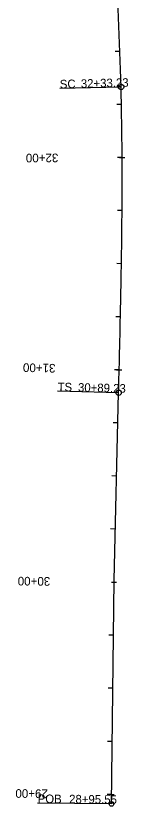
# Model space of a CAD drawing. Extents: x 21487884 to 21488802, y 8074558 to 8076894.
# Drawn here: x 21488108.5 to 21488161.4, y 8074558.2 to 8074930.5 of the extents above; entities that cross this region are included whole.
import ezdxf

# ---------------------------------------------------------------- set-up
doc = ezdxf.new("R2010")
doc.units = 0
for name, color, linetype in [('Default', 7, 'Continuous'), ('PS_BOLT', 7, 'Continuous'), ('PS_DIM', 7, 'Continuous'), ('PS_MID', 7, 'Continuous'), ('PS_SHAPE', 7, 'Continuous')]:
    doc.layers.add(name, color=color, linetype=linetype)

msp = doc.modelspace()

# ---------------------------------------------------------------- linework, layer by layer
at = {"layer": 'Default'}
msp.add_line((21488154.77, 8074664.65), (21488156.95, 8074752.94), dxfattribs=at)
msp.add_arc((21486726.15, 8074860.23), 1432.4, 1.46747, 6.70748, dxfattribs=at)
msp.add_open_spline([(21488156.95, 8074752.94), (21488157.09, 8074758.94), (21488157.39, 8074770.93), (21488157.94, 8074794.93), (21488158.5, 8074824.92), (21488158.67, 8074854.92), (21488158.47, 8074878.92), (21488158.24, 8074890.92), (21488158.08, 8074896.92)], degree=3, dxfattribs=at)
at = {"layer": 'PS_BOLT'}
for p, q in [((21488158.58, 8074863.69), (21488156.4, 8074863.68)), ((21488157.21, 8074763.7), (21488155.03, 8074763.76)), ((21488153.54, 8074663.75), (21488155.98, 8074663.72)), ((21488153.65, 8074563.74), (21488151.47, 8074563.76))]:
    msp.add_line(p, q, dxfattribs=at)
at = {"layer": 'PS_DIM'}
for p, q in [((21488158.08, 8074896.92), (21488129.29, 8074896.18)), ((21488158.08, 8074896.92), (21488129.29, 8074896.18)), ((21488156.95, 8074752.94), (21488128.16, 8074753.65)), ((21488153.61, 8074559.29), (21488118.81, 8074559.67))]:
    msp.add_line(p, q, dxfattribs=at)
for centre, radius in [((21488158.08, 8074896.92), 1.25), ((21488158.08, 8074896.92), 1.25), ((21488156.95, 8074752.94), 1.25), ((21488153.61, 8074559.29), 1.07)]:
    msp.add_circle(centre, radius, dxfattribs=at)
at = {"layer": 'PS_MID'}
for p, q in [((21488157.56, 8074913.68), (21488155.37, 8074913.6)), ((21488158.27, 8074888.69), (21488156.09, 8074888.64)), ((21488157.36, 8074863.68), (21488159.8, 8074863.7)), ((21488158.55, 8074838.69), (21488156.37, 8074838.71)), ((21488158.26, 8074813.69), (21488156.08, 8074813.73)), ((21488157.79, 8074788.7), (21488155.61, 8074788.74)), ((21488155.99, 8074763.73), (21488158.44, 8074763.67)), ((21488156.6, 8074738.71), (21488154.41, 8074738.76)), ((21488155.98, 8074713.72), (21488153.8, 8074713.77)), ((21488155.36, 8074688.73), (21488153.18, 8074688.78)), ((21488153.54, 8074663.75), (21488155.98, 8074663.72)), ((21488154.48, 8074638.74), (21488152.3, 8074638.76)), ((21488154.21, 8074613.74), (21488152.02, 8074613.76)), ((21488153.93, 8074588.74), (21488151.75, 8074588.76)), ((21488152.43, 8074563.75), (21488154.88, 8074563.73))]:
    msp.add_line(p, q, dxfattribs=at)
at = {"layer": 'PS_SHAPE'}
for p, q in [((21488154.77, 8074664.65), (21488156.95, 8074752.94)), ((21488154.77, 8074664.65), (21488156.95, 8074752.94)), ((21488153.61, 8074559.29), (21488154.77, 8074664.65)), ((21488153.61, 8074559.29), (21488154.77, 8074664.65))]:
    msp.add_line(p, q, dxfattribs=at)
msp.add_arc((21486726.15, 8074860.23), 1432.4, 1.46747, 6.70748, dxfattribs=at)
msp.add_arc((21486726.15, 8074860.23), 1432.4, 1.46747, 6.70748, dxfattribs=at)
msp.add_open_spline([(21488156.95, 8074752.94), (21488157.09, 8074758.94), (21488157.39, 8074770.93), (21488157.94, 8074794.93), (21488158.5, 8074824.92), (21488158.67, 8074854.92), (21488158.47, 8074878.92), (21488158.24, 8074890.92), (21488158.08, 8074896.92)], degree=3, dxfattribs=at)
msp.add_open_spline([(21488156.95, 8074752.94), (21488157.09, 8074758.94), (21488157.39, 8074770.93), (21488157.94, 8074794.93), (21488158.5, 8074824.92), (21488158.67, 8074854.92), (21488158.47, 8074878.92), (21488158.24, 8074890.92), (21488158.08, 8074896.92)], degree=3, dxfattribs=at)

# ---------------------------------------------------------------- texts
at = {"layer": 'PS_BOLT'}
msp.add_text('30+00', height=4.08, rotation=179.3665, dxfattribs=at).set_placement((21488124.78, 8074666.11))
at = {"layer": 'PS_DIM'}
for s, rotation, p in [('32+33.23', 1.4675, (21488139.2, 8074896.51)), ('32+33.23', 1.4675, (21488139.2, 8074896.51)), ('SC', 1.4675, (21488129.29, 8074896.26)), ('SC', 1.4675, (21488129.29, 8074896.26)), ('TS', 358.5875, (21488128.16, 8074753.73)), ('30+89.23', 358.5875, (21488137.78, 8074753.49)), ('POB ', 359.3665, (21488118.81, 8074559.75)), ('28+95.55', 359.3665, (21488133.62, 8074559.59))]:
    msp.add_text(s, height=4.008, rotation=rotation, dxfattribs=at).set_placement(p)
at = {"layer": 'PS_MID'}
for s, rotation, p in [('32+00', 180.2916, (21488128.57, 8074865.58)), ('31+00', 178.6036, (21488127.27, 8074766.47)), ('30+00', 179.3665, (21488124.78, 8074666.11)), ('29+00', 179.3665, (21488123.68, 8074566.11))]:
    msp.add_text(s, height=4.08, rotation=rotation, dxfattribs=at).set_placement(p)

doc.saveas('drawing.dxf')
